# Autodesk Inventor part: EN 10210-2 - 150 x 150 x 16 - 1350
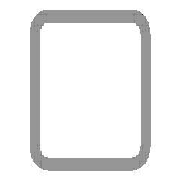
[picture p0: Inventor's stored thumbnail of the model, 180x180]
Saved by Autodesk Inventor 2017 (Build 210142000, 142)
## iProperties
Created: 2017-11
Part Number: EN 10210-2 - 150 x 150 x 16 - 1350
Material: Steel, Mild
Description: Tube
Document SubType Name: Modeling
Standard: DIN
Designer: iusti
Standard Revision: 2006-07
Standards Organization: DIN
Language: en-US
Size Designation: 150 x 150 x 16
Categories: <MemberInstance><Categories><Category DisplayName="Structural Shapes" InternalName="089c4875-fa83-4c05-b084-43b9cc11f5ed" Mnemonic="GRDR"><CategoryParameter Dis
Stock Number: 150 x 150 x 16
Mass: 87973.1 g
Surface Area: 13710.9 cm^2
Volume: 11206.8 cm^3
Density: 7.85 g/cm^3
Appearance: Semi-Polished
_CCFamilyMember: 70
_CCFamilyDisplayName: DIN EN 10210-2 (Square) - Tube — Sizes in parentheses have been withdrawn
_FrameMemberDoc: Frame Member File
_Version: 15.0.0
_GetPNFromCC: 1
IsCustomPart: 1
Author: iusti
G_L: 1350.000 mm
G_W: 150.000 mm
G_H: 150.000 mm
+10D55805-8129-426B-ACBA-EE902965C192+CUTDETAIL1: Cut
+790C41B2-1AF7-48DC-9C9E-A9B8D9A07545+CUTDETAIL2: Cut
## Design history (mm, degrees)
node "Start plane"
node "End plane"
sketch "Sketch"
  geometry: L1 (-75, -51)-(-75, 51); L2 (-51, 75)-(51, 75); L3 (75, 51)-(75, -51); L4 (51, -75)-(-51, -75); L5 (-43, 59)-(43, 59); L6 (59, 43)-(59, -43); L7 (43, -59)-(-43, -59); L8 (-59, -43)-(-59, 43); L9 (0, 111.959)-(0, -111.959) reference; L10 (-111.959, 0)-(111.959, 0) reference; A1 r 24 centre (-51, -51) between (-75, -51) and (-51, -75); A2 r 24 centre (-51, 51) between (-51, 75) and (-75, 51); A3 r 24 centre (51, 51) between (75, 51) and (51, 75); A4 r 24 centre (51, -51) between (51, -75) and (75, -51); A5 r 16 centre (-43, -43) between (-59, -43) and (-43, -59); A6 r 16 centre (-43, 43) between (-43, 59) and (-59, 43); A7 r 16 centre (43, 43) between (59, 43) and (43, 59); A8 r 16 centre (43, -43) between (43, -59) and (59, -43)
  constraints: 16 end point, 16 point on circle, 16 tangent, 8 centre point, 6 equal radius, 4 parallel, 2 perpendicular, 2 other
  dimensions: "d7" = 24 radius of A1 (= G_IR); "d10" = 150 distance between parallel lines of L2 L4 (= G_H); "d11" = 150 distance between parallel lines of L1 L3 (= G_W); "d12" = 16 distance between parallel lines of L3 L6 (= G_T); "d15" = 75 distance between parallel lines of L2 L10 (= 0.5 x d10); "d16" = 75 distance between parallel lines of L9 L3 (= 0.5 x d11); "d19" = 16 radius of A5 (= G_T); "d20" = 16 distance between parallel lines of L4 L7 (= G_T)
extrude "Body" new body sketch "Sketch" stored distance "d3" = 1350 (= G_L); taper "d4" = 0 deg
node "Driven Length"
  sketch "Sketch3"
    geometry: L1 (0, 0)-(10, 0) reference
    constraints: 2 end point, 1 horizontal
  workplane "Work Plane3"
  sketch "Sketch4"
    geometry: L1 (-2, 75)-(12, 75) reference; L2 (-2, 1425)-(12, 1425) reference
    dimensions: "d18" = 1350 distance between parallel lines of L1 L2 (derived)
workplane "Work Plane4"
split "Split1"
workplane "Work Plane5"
split "Split2"
body "Solid1"
other parameters: "G_W" = 150 [user parameter; used in 1 equation term], "G_H" = 150 [user parameter; used in 1 equation term], "G_T" = 16 [user parameter; used in 3 equation terms], "G_IR" = 24 [user parameter; used in 1 equation term], "G_L" = 1350 (= d18) [user parameter; used in 1 equation term], "G_OFFSET_START" = -75 [user parameter; used in 1 equation term], "G_OFFSET_END" = -75 [user parameter; used in 1 equation term], "d13" = 75 (= -G_OFFSET_START), "d14" = 1425 (= G_OFFSET_END + B_L), "d17" = 90 deg
